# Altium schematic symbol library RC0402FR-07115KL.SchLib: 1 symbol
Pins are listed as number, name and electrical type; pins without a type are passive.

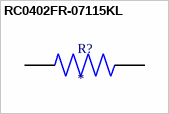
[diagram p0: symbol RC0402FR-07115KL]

## RC0402FR-07115KL
designator R?
115 kOhms Â±1% 0.063W, 1/16W Chip Resistor 0402 (1005 Metric) Moisture Resistant Thick Film; MF: Yageo; MP: RC0402FR-07115KL
footprint RESC1005X40N
pins: 1, 2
